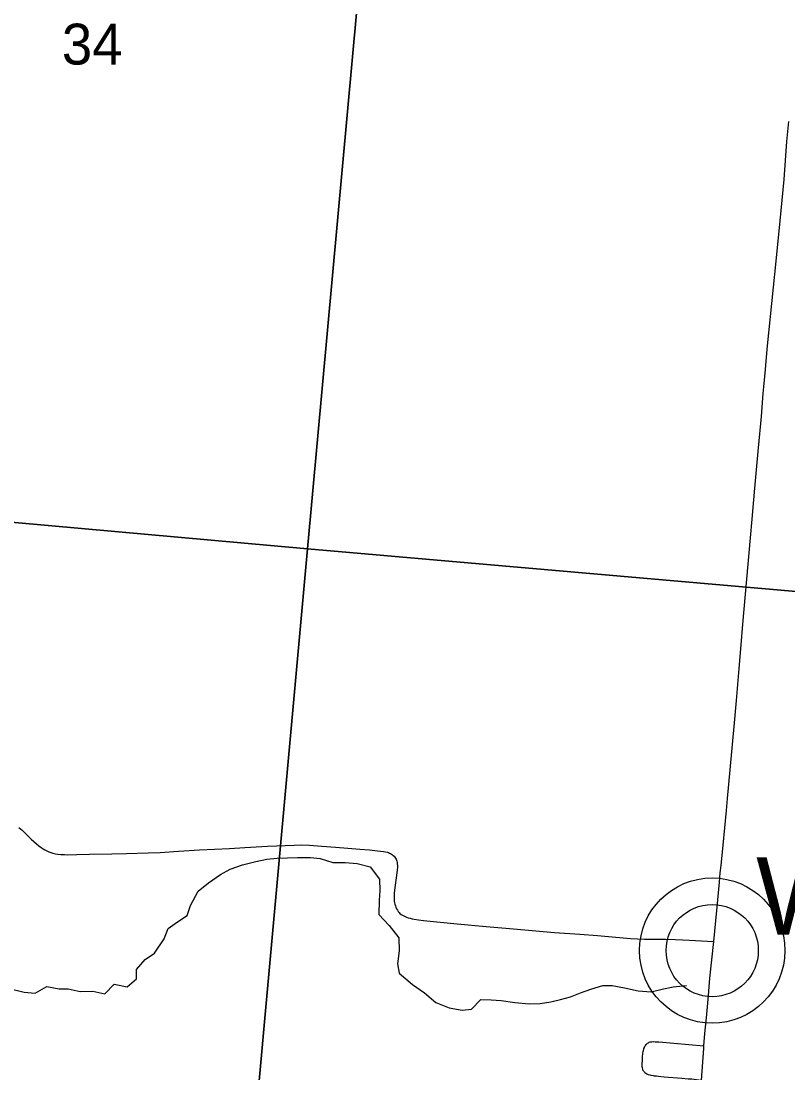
# Model space of a CAD drawing. Extents: x -38.1 to 35.9, y -2.7 to 28.5.
# Drawn here: x 10.974 to 11.759, y 17.716 to 18.793 of the extents above; entities that cross this region are included whole.
import ezdxf

# ---------------------------------------------------------------- set-up
doc = ezdxf.new("R2010")
doc.units = 0
for name, color, linetype in [('GM_X_County_ROW', 7, 'Continuous'), ('GM_X_Interchange_Ramps', 7, 'Continuous'), ('GM_X_Major_River_Text', 7, 'Continuous'), ('GM_X_Minor_River', 7, 'Continuous'), ('GM_X_Section', 7, 'Continuous'), ('GM_X_State_Location', 7, 'Continuous'), ('GM_X_Township_Subdivision_Text', 7, 'Continuous'), ('GM_X_US_Route', 7, 'Continuous')]:
    doc.layers.add(name, color=color, linetype=linetype)

msp = doc.modelspace()

# ---------------------------------------------------------------- linework, layer by layer
at = {"layer": 'GM_X_County_ROW'}
msp.add_line((11.6814, 17.8409), (11.6814, 17.8409), dxfattribs=at)
at = {"layer": 'GM_X_Interchange_Ramps'}
msp.add_lwpolyline([(11.6704, 17.7083), (11.6727, 17.7407), (11.6729, 17.7433), (11.674, 17.756), (11.6756, 17.772), (11.6763, 17.7795), (11.6776, 17.7949), (11.6791, 17.8126), (11.6829, 17.8501), (11.686, 17.8821), (11.6887, 17.9109), (11.6896, 17.9204), (11.6904, 17.928), (11.6925, 17.9488), (11.6943, 17.9666), (11.6961, 17.9845), (11.697, 17.9968), (11.6997, 18.0259), (11.7042, 18.0741), (11.7062, 18.097), (11.709, 18.1299), (11.7111, 18.154), (11.7129, 18.175), (11.7154, 18.206), (11.7207, 18.2635), (11.7224, 18.2827), (11.725, 18.3143), (11.7288, 18.3558), (11.7318, 18.3879), (11.7337, 18.4115), (11.7342, 18.4181), (11.7352, 18.4289), (11.7358, 18.4359), (11.7377, 18.4566), (11.7443, 18.5203), (11.7466, 18.5434), (11.7508, 18.5883), (11.7549, 18.6304), (11.7579, 18.6694), (11.7598, 18.6898)], dxfattribs=at)
at = {"layer": 'GM_X_Major_River_Text'}
for points in [[(10.9715, 17.9671), (10.9749, 17.9641), (10.9842, 17.9549), (10.9894, 17.9503), (10.9919, 17.9483), (10.9944, 17.9465), (10.9963, 17.9452), (10.9981, 17.9441), (11.0001, 17.943), (11.0021, 17.942), (11.0042, 17.9413), (11.0064, 17.9407), (11.0089, 17.9401), (11.0114, 17.9398), (11.0146, 17.9394), (11.0181, 17.9392), (11.0214, 17.9391), (11.0307, 17.9393), (11.0438, 17.9396), (11.0667, 17.9401), (11.0816, 17.9404)], [(11.0816, 17.9404), (11.1039, 17.941), (11.1163, 17.9415), (11.135, 17.9427), (11.1566, 17.9441), (11.187, 17.9456), (11.2029, 17.9464), (11.226, 17.9478), (11.2534, 17.949), (11.2612, 17.9492), (11.2689, 17.949), (11.2818, 17.9479), (11.2958, 17.9467), (11.3083, 17.9457), (11.3207, 17.9447), (11.3305, 17.9439), (11.3386, 17.9432), (11.3419, 17.9428), (11.3447, 17.9425), (11.347, 17.9421), (11.3488, 17.9416), (11.35, 17.9412), (11.351, 17.9408), (11.3521, 17.9403), (11.3531, 17.9397), (11.3541, 17.939), (11.3549, 17.9383), (11.3557, 17.9375), (11.3565, 17.9366), (11.3571, 17.9357), (11.3577, 17.9346), (11.3582, 17.9335), (11.3585, 17.9325), (11.3588, 17.9311), (11.3589, 17.9296), (11.3591, 17.928), (11.359, 17.9262), (11.3588, 17.9236), (11.3585, 17.9204), (11.3562, 17.9026), (11.3559, 17.8997), (11.3557, 17.8969), (11.3557, 17.8951), (11.3558, 17.8931), (11.3559, 17.8915), (11.3562, 17.8899), (11.3565, 17.8884), (11.357, 17.8868), (11.3576, 17.8853), (11.3583, 17.8838), (11.3591, 17.8823), (11.36, 17.881), (11.3609, 17.8799), (11.3617, 17.879), (11.363, 17.878), (11.3642, 17.8772), (11.3655, 17.8764), (11.3669, 17.8757), (11.3684, 17.8751), (11.3701, 17.8745), (11.3721, 17.874), (11.3741, 17.8735), (11.3762, 17.8731), (11.3807, 17.8724), (11.3859, 17.8717), (11.4203, 17.8683), (11.45, 17.8655), (11.4778, 17.8631), (11.5199, 17.8593), (11.5459, 17.8576), (11.5638, 17.8562), (11.5978, 17.8534), (11.6121, 17.8527), (11.6231, 17.8525), (11.6334, 17.8525), (11.6439, 17.8523), (11.6581, 17.8517), (11.6764, 17.8505), (11.6829, 17.8501)], [(11.6109, 17.7178), (11.6105, 17.7185), (11.6102, 17.7193), (11.6099, 17.7209), (11.6098, 17.7219), (11.6098, 17.723), (11.6098, 17.7251), (11.6099, 17.7285), (11.6101, 17.7321), (11.6104, 17.7354), (11.6108, 17.7377), (11.611, 17.7385), (11.6114, 17.7401), (11.6115, 17.7407), (11.6119, 17.7416), (11.6122, 17.7423), (11.6126, 17.7431), (11.613, 17.7438), (11.6138, 17.7448), (11.6147, 17.7457), (11.6153, 17.7462)], [(11.6153, 17.7462), (11.6161, 17.7466), (11.6167, 17.747), (11.6178, 17.7474), (11.6187, 17.7476), (11.6196, 17.7476), (11.621, 17.7477), (11.6229, 17.7476), (11.6269, 17.7473), (11.6729, 17.7433)], [(11.6109, 17.7178), (11.6113, 17.7172), (11.6117, 17.7167), (11.6123, 17.7161), (11.6133, 17.7154), (11.6146, 17.7147), (11.6159, 17.7141), (11.6175, 17.7136), (11.6187, 17.7133), (11.621, 17.7129), (11.622, 17.7127), (11.6243, 17.7125), (11.6263, 17.7122), (11.6322, 17.7117), (11.6503, 17.7102), (11.6569, 17.7097), (11.6606, 17.7094), (11.6653, 17.7089), (11.6704, 17.7083)]]:
    msp.add_lwpolyline(points, dxfattribs=at)
at = {"layer": 'GM_X_Section'}
for points in [[(10.9644, 17.8014), (10.9769, 17.7982), (10.9883, 17.7973), (11.0001, 17.804), (11.0126, 17.8016), (11.0221, 17.8018), (11.0342, 17.799), (11.0471, 17.7993), (11.0595, 17.7965), (11.0691, 17.8066), (11.0824, 17.8038), (11.0919, 17.812), (11.0921, 17.8215), (11.1009, 17.8316), (11.1105, 17.8384), (11.1201, 17.8531), (11.1244, 17.8636), (11.134, 17.8704), (11.1439, 17.8767), (11.1471, 17.8869), (11.1552, 17.9016), (11.1656, 17.9102), (11.1778, 17.9188), (11.1877, 17.9244), (11.2003, 17.9288), (11.214, 17.9321), (11.2254, 17.9346), (11.236, 17.9356), (11.2466, 17.9358), (11.2569, 17.9361), (11.2702, 17.9363), (11.28, 17.9351), (11.2929, 17.9311), (11.3057, 17.931), (11.3179, 17.9301), (11.3311, 17.9265), (11.3408, 17.9142), (11.341, 17.9021), (11.3405, 17.8926), (11.34, 17.8778), (11.3505, 17.8666), (11.3606, 17.854), (11.3608, 17.8407), (11.3591, 17.8274), (11.3609, 17.8179), (11.3744, 17.8063), (11.3868, 17.7975), (11.3984, 17.7878), (11.412, 17.7824), (11.4253, 17.7799), (11.4348, 17.7809), (11.4444, 17.7907), (11.455, 17.7906), (11.4652, 17.7897), (11.4792, 17.7876), (11.494, 17.7863), (11.5054, 17.7866), (11.516, 17.7883), (11.5259, 17.7909)], [(11.5259, 17.7909), (11.5362, 17.7934), (11.5465, 17.7975), (11.5571, 17.8015), (11.5693, 17.8052), (11.5788, 17.805), (11.5916, 17.8026), (11.6056, 17.7998), (11.6189, 17.7985), (11.6315, 17.8018), (11.6413, 17.8039), (11.655, 17.8053)]]:
    msp.add_lwpolyline(points, dxfattribs=at)
at = {"layer": 'GM_X_State_Location'}
for radius in [0.0744, 0.0472]:
    msp.add_circle((11.6814, 17.8409), radius, dxfattribs=at)
at = {"layer": 'GM_X_US_Route'}
for points in [[(11.3585, 19.2527), (11.2671, 18.2524), (10.6712, 18.3059)], [(10.6712, 18.3059), (11.2671, 18.2524), (11.175, 17.2383)]]:
    msp.add_lwpolyline(points, dxfattribs=at)
for points in [[(11.3585, 19.2527), (12.358, 19.1694), (12.2713, 18.1647), (11.2671, 18.2524)], [(11.2671, 18.2524), (12.2713, 18.1647), (12.1826, 17.1517), (11.6659, 17.2023), (11.175, 17.2383)]]:
    msp.add_lwpolyline(points, close=True, dxfattribs=at)

# ---------------------------------------------------------------- texts
at = {"layer": 'GM_X_Minor_River'}
msp.add_text('34', height=0.04186, rotation=0, dxfattribs=at).set_placement((11.0155, 18.7482))
at = {"layer": 'GM_X_Township_Subdivision_Text'}
msp.add_text('West Charleston', height=0.078977, rotation=0, dxfattribs=at).set_placement((11.7264, 17.8573))

doc.saveas('drawing.dxf')
